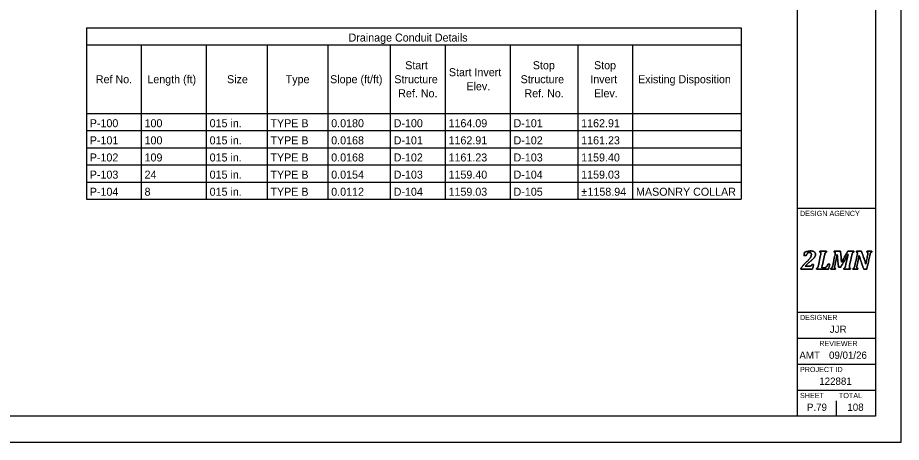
# Model space of a CAD drawing. Extents: x 0 to 34, y 0 to 22.
# Drawn here: x 17 to 34, y 0 to 8.16 of the extents above; entities that cross this region are included whole.
import ezdxf

# ---------------------------------------------------------------- set-up
doc = ezdxf.new("R2010")
doc.units = 0
for name, color, linetype in [('PF_P_Sta_Elev_Text', 7, 'Continuous'), ('SH_Border', 7, 'Continuous'), ('SH_Cut_Line', 7, 'Continuous'), ('SH_Data', 7, 'Continuous')]:
    doc.layers.add(name, color=color, linetype=linetype)

msp = doc.modelspace()

# ---------------------------------------------------------------- linework, layer by layer
at = {"layer": 'PF_P_Sta_Elev_Text'}
for p, q in [((18.321, 7.968), (30.921, 7.968)), ((18.321, 7.968), (18.321, 4.674)), ((30.921, 7.968), (30.921, 4.674)), ((18.321, 7.639), (30.921, 7.639)), ((19.376, 7.639), (19.376, 4.674)), ((20.627, 7.639), (20.627, 4.674)), ((21.797, 7.639), (21.797, 4.674)), ((22.966, 7.639), (22.966, 4.674)), ((24.169, 7.639), (24.169, 4.674)), ((25.223, 7.639), (25.223, 4.674)), ((26.474, 7.639), (26.474, 4.674)), ((27.776, 7.639), (27.776, 4.674)), ((28.83, 7.639), (28.83, 4.674)), ((18.321, 6.321), (30.921, 6.321)), ((18.321, 5.992), (30.921, 5.992)), ((18.321, 5.662), (30.921, 5.662)), ((18.321, 5.333), (30.921, 5.333)), ((18.321, 5.003), (30.921, 5.003)), ((18.321, 4.674), (30.921, 4.674))]:
    msp.add_line(p, q, dxfattribs=at)
at = {"layer": 'SH_Border'}
for p, q in [((32, 0.5), (32, 21.5)), ((32, 4.5), (33.5, 4.5)), ((32, 2.5), (33.5, 2.5)), ((32, 2), (33.5, 2)), ((32, 1.5), (33.5, 1.5)), ((32, 1), (33.5, 1))]:
    msp.add_line(p, q, dxfattribs=at)
msp.add_lwpolyline([(1.5, 21.5), (33.5, 21.5), (33.5, 0.5), (1.5, 0.5)], close=True, dxfattribs=at)
at = {"layer": 'SH_Cut_Line'}
msp.add_lwpolyline([(0, 0), (34, 0), (34, 22), (0, 22)], close=True, dxfattribs=at)
at = {"layer": 'SH_Data'}
for p, q in [((32.75, 3.5), (32.75, 3.5)), ((32.75, 0.5), (32.75, 0.8)), ((32.375, 0.675), (32.375, 0.675))]:
    msp.add_line(p, q, dxfattribs=at)
for points in [[(32.237, 3.388), (32.246, 3.388), (32.253, 3.389), (32.258, 3.39), (32.263, 3.392), (32.267, 3.394), (32.27, 3.397), (32.273, 3.401), (32.277, 3.408), (32.281, 3.417), (32.281, 3.417), (32.312, 3.417), (32.312, 3.417), (32.312, 3.417), (32.29, 3.326), (32.29, 3.326), (32.29, 3.326), (32.066, 3.326), (32.066, 3.326), (32.066, 3.326), (32.069, 3.343), (32.069, 3.343), (32.078, 3.358), (32.091, 3.375), (32.106, 3.394), (32.122, 3.412), (32.144, 3.435), (32.172, 3.462), (32.197, 3.486), (32.217, 3.506), (32.23, 3.521), (32.243, 3.537), (32.253, 3.551), (32.259, 3.566), (32.266, 3.58), (32.269, 3.595), (32.269, 3.61), (32.269, 3.622), (32.266, 3.632), (32.26, 3.64), (32.253, 3.647), (32.245, 3.65), (32.234, 3.65), (32.22, 3.65), (32.208, 3.646), (32.198, 3.636), (32.188, 3.627), (32.18, 3.613), (32.172, 3.593), (32.172, 3.593), (32.126, 3.593), (32.126, 3.593), (32.126, 3.593), (32.14, 3.654), (32.14, 3.654), (32.166, 3.663), (32.188, 3.669), (32.205, 3.673), (32.223, 3.676), (32.24, 3.678), (32.258, 3.678), (32.278, 3.678), (32.295, 3.675), (32.309, 3.669), (32.322, 3.664), (32.332, 3.656), (32.339, 3.646), (32.345, 3.637), (32.348, 3.626), (32.348, 3.613), (32.348, 3.602), (32.346, 3.591), (32.342, 3.581), (32.339, 3.571), (32.333, 3.56), (32.324, 3.549), (32.315, 3.539), (32.304, 3.526), (32.289, 3.513), (32.275, 3.499), (32.254, 3.482), (32.228, 3.46), (32.216, 3.45), (32.202, 3.438), (32.188, 3.425), (32.174, 3.412), (32.162, 3.4), (32.154, 3.391), (32.154, 3.391), (32.153, 3.388), (32.153, 3.388), (32.153, 3.388), (32.237, 3.388), (32.237, 3.388)], [(32.237, 3.388), (32.237, 3.388), (32.153, 3.388), (32.153, 3.388), (32.153, 3.388), (32.154, 3.391), (32.154, 3.391), (32.162, 3.4), (32.174, 3.412), (32.188, 3.425), (32.202, 3.438), (32.216, 3.45), (32.228, 3.46), (32.254, 3.482), (32.275, 3.499), (32.289, 3.513), (32.304, 3.526), (32.315, 3.539), (32.324, 3.549), (32.333, 3.56), (32.339, 3.571), (32.342, 3.581), (32.346, 3.591), (32.348, 3.602), (32.348, 3.613), (32.348, 3.626), (32.345, 3.637), (32.339, 3.646), (32.332, 3.656), (32.322, 3.664), (32.309, 3.669), (32.295, 3.675), (32.278, 3.678), (32.258, 3.678), (32.24, 3.678), (32.223, 3.676), (32.205, 3.673), (32.188, 3.669), (32.166, 3.663), (32.14, 3.654), (32.14, 3.654), (32.126, 3.593), (32.126, 3.593), (32.126, 3.593), (32.172, 3.593), (32.172, 3.593), (32.18, 3.613), (32.188, 3.627), (32.198, 3.636), (32.208, 3.646), (32.22, 3.65), (32.234, 3.65), (32.245, 3.65), (32.253, 3.647), (32.26, 3.64), (32.266, 3.632), (32.269, 3.622), (32.269, 3.61), (32.269, 3.595), (32.266, 3.58), (32.259, 3.566), (32.253, 3.551), (32.243, 3.537), (32.23, 3.521), (32.217, 3.506), (32.197, 3.486), (32.172, 3.462), (32.144, 3.435), (32.122, 3.412), (32.106, 3.394), (32.091, 3.375), (32.078, 3.358), (32.069, 3.343), (32.069, 3.343), (32.066, 3.326), (32.066, 3.326), (32.066, 3.326), (32.29, 3.326), (32.29, 3.326), (32.29, 3.326), (32.312, 3.417), (32.312, 3.417), (32.312, 3.417), (32.281, 3.417), (32.281, 3.417), (32.277, 3.408), (32.273, 3.401), (32.27, 3.397), (32.267, 3.394), (32.263, 3.392), (32.258, 3.39), (32.253, 3.389), (32.246, 3.388), (32.237, 3.388)], [(32.518, 3.356), (32.527, 3.356), (32.533, 3.357), (32.538, 3.358), (32.542, 3.36), (32.546, 3.362), (32.55, 3.365), (32.554, 3.368), (32.558, 3.372), (32.562, 3.377), (32.567, 3.382), (32.571, 3.388), (32.576, 3.397), (32.58, 3.405), (32.585, 3.415), (32.589, 3.427), (32.589, 3.427), (32.624, 3.427), (32.624, 3.427), (32.624, 3.427), (32.598, 3.326), (32.598, 3.326), (32.598, 3.326), (32.365, 3.326), (32.365, 3.326), (32.365, 3.326), (32.369, 3.343), (32.369, 3.343), (32.376, 3.345), (32.381, 3.348), (32.385, 3.351), (32.389, 3.355), (32.392, 3.36), (32.395, 3.366), (32.398, 3.373), (32.4, 3.382), (32.403, 3.395), (32.403, 3.395), (32.449, 3.605), (32.449, 3.605), (32.452, 3.615), (32.453, 3.625), (32.453, 3.635), (32.453, 3.642), (32.451, 3.647), (32.448, 3.651), (32.444, 3.654), (32.439, 3.656), (32.432, 3.657), (32.432, 3.657), (32.435, 3.674), (32.435, 3.674), (32.435, 3.674), (32.563, 3.674), (32.563, 3.674), (32.563, 3.674), (32.559, 3.657), (32.559, 3.657), (32.552, 3.655), (32.547, 3.652), (32.543, 3.649), (32.539, 3.645), (32.536, 3.64), (32.533, 3.634), (32.531, 3.627), (32.528, 3.618), (32.525, 3.605), (32.525, 3.605), (32.47, 3.356), (32.47, 3.356), (32.47, 3.356), (32.518, 3.356), (32.518, 3.356)], [(32.518, 3.356), (32.518, 3.356), (32.47, 3.356), (32.47, 3.356), (32.47, 3.356), (32.525, 3.605), (32.525, 3.605), (32.528, 3.618), (32.531, 3.627), (32.533, 3.634), (32.536, 3.64), (32.539, 3.645), (32.543, 3.649), (32.547, 3.652), (32.552, 3.655), (32.559, 3.657), (32.559, 3.657), (32.563, 3.674), (32.563, 3.674), (32.563, 3.674), (32.435, 3.674), (32.435, 3.674), (32.435, 3.674), (32.432, 3.657), (32.432, 3.657), (32.439, 3.656), (32.444, 3.654), (32.448, 3.651), (32.451, 3.647), (32.453, 3.642), (32.453, 3.635), (32.453, 3.625), (32.452, 3.615), (32.449, 3.605), (32.449, 3.605), (32.403, 3.395), (32.403, 3.395), (32.4, 3.382), (32.398, 3.373), (32.395, 3.366), (32.392, 3.36), (32.389, 3.355), (32.385, 3.351), (32.381, 3.348), (32.376, 3.345), (32.369, 3.343), (32.369, 3.343), (32.365, 3.326), (32.365, 3.326), (32.365, 3.326), (32.598, 3.326), (32.598, 3.326), (32.598, 3.326), (32.624, 3.427), (32.624, 3.427), (32.624, 3.427), (32.589, 3.427), (32.589, 3.427), (32.585, 3.415), (32.58, 3.405), (32.576, 3.397), (32.571, 3.388), (32.567, 3.382), (32.562, 3.377), (32.558, 3.372), (32.554, 3.368), (32.55, 3.365), (32.546, 3.362), (32.542, 3.36), (32.538, 3.358), (32.533, 3.357), (32.527, 3.356), (32.518, 3.356)], [(32.829, 3.674), (32.829, 3.674), (32.849, 3.461), (32.849, 3.461), (32.849, 3.461), (32.969, 3.674), (32.969, 3.674), (32.969, 3.674), (33.087, 3.674), (33.087, 3.674), (33.087, 3.674), (33.084, 3.657), (33.084, 3.657), (33.077, 3.655), (33.071, 3.652), (33.067, 3.649), (33.064, 3.645), (33.06, 3.64), (33.058, 3.634), (33.055, 3.627), (33.052, 3.618), (33.05, 3.605), (33.05, 3.605), (33.003, 3.395), (33.003, 3.395), (33.002, 3.39), (33.002, 3.387), (33.001, 3.384), (33.001, 3.382), (33.001, 3.379), (33, 3.376), (33, 3.373), (33, 3.369), (33, 3.365), (33, 3.358), (33.002, 3.353), (33.005, 3.349), (33.008, 3.346), (33.014, 3.344), (33.021, 3.343), (33.021, 3.343), (33.018, 3.326), (33.018, 3.326), (33.018, 3.326), (32.89, 3.326), (32.89, 3.326), (32.89, 3.326), (32.893, 3.343), (32.893, 3.343), (32.9, 3.345), (32.906, 3.348), (32.91, 3.351), (32.914, 3.355), (32.917, 3.36), (32.919, 3.366), (32.922, 3.373), (32.925, 3.382), (32.928, 3.395), (32.928, 3.395), (32.951, 3.502), (32.951, 3.502), (32.954, 3.513), (32.957, 3.529), (32.962, 3.548), (32.967, 3.568), (32.972, 3.588), (32.978, 3.609), (32.978, 3.609), (32.973, 3.609), (32.973, 3.609), (32.965, 3.594), (32.957, 3.579), (32.948, 3.563), (32.948, 3.563), (32.833, 3.364), (32.833, 3.364), (32.833, 3.364), (32.792, 3.364), (32.792, 3.364), (32.792, 3.364), (32.775, 3.518), (32.775, 3.518), (32.773, 3.537), (32.772, 3.554), (32.77, 3.569), (32.769, 3.583), (32.768, 3.597), (32.768, 3.611), (32.768, 3.611), (32.764, 3.611), (32.764, 3.611), (32.761, 3.596), (32.758, 3.578), (32.755, 3.558), (32.751, 3.538), (32.747, 3.521), (32.744, 3.507), (32.744, 3.507), (32.72, 3.395), (32.72, 3.395), (32.719, 3.39), (32.718, 3.387), (32.718, 3.384), (32.717, 3.382), (32.717, 3.379), (32.717, 3.376), (32.717, 3.373), (32.716, 3.369), (32.716, 3.365), (32.716, 3.358), (32.718, 3.353), (32.721, 3.349), (32.725, 3.346), (32.73, 3.344), (32.738, 3.343), (32.738, 3.343), (32.734, 3.326), (32.734, 3.326), (32.734, 3.326), (32.641, 3.326), (32.641, 3.326), (32.641, 3.326), (32.644, 3.343), (32.644, 3.343), (32.651, 3.345), (32.657, 3.348), (32.661, 3.351), (32.665, 3.355), (32.668, 3.36), (32.67, 3.366), (32.673, 3.373), (32.676, 3.382), (32.679, 3.395), (32.679, 3.395), (32.725, 3.605), (32.725, 3.605), (32.727, 3.615), (32.728, 3.625), (32.728, 3.635), (32.728, 3.642), (32.727, 3.647), (32.723, 3.651), (32.72, 3.654), (32.715, 3.656), (32.707, 3.657), (32.707, 3.657), (32.711, 3.674), (32.711, 3.674), (32.711, 3.674), (32.829, 3.674), (32.829, 3.674)], [(32.829, 3.674), (32.829, 3.674), (32.711, 3.674), (32.711, 3.674), (32.711, 3.674), (32.707, 3.657), (32.707, 3.657), (32.715, 3.656), (32.72, 3.654), (32.723, 3.651), (32.727, 3.647), (32.728, 3.642), (32.728, 3.635), (32.728, 3.625), (32.727, 3.615), (32.725, 3.605), (32.725, 3.605), (32.679, 3.395), (32.679, 3.395), (32.676, 3.382), (32.673, 3.373), (32.67, 3.366), (32.668, 3.36), (32.665, 3.355), (32.661, 3.351), (32.657, 3.348), (32.651, 3.345), (32.644, 3.343), (32.644, 3.343), (32.641, 3.326), (32.641, 3.326), (32.641, 3.326), (32.734, 3.326), (32.734, 3.326), (32.734, 3.326), (32.738, 3.343), (32.738, 3.343), (32.73, 3.344), (32.725, 3.346), (32.721, 3.349), (32.718, 3.353), (32.716, 3.358), (32.716, 3.365), (32.716, 3.369), (32.717, 3.373), (32.717, 3.376), (32.717, 3.379), (32.717, 3.382), (32.718, 3.384), (32.718, 3.387), (32.719, 3.39), (32.72, 3.395), (32.72, 3.395), (32.744, 3.507), (32.744, 3.507), (32.747, 3.521), (32.751, 3.538), (32.755, 3.558), (32.758, 3.578), (32.761, 3.596), (32.764, 3.611), (32.764, 3.611), (32.768, 3.611), (32.768, 3.611), (32.768, 3.597), (32.769, 3.583), (32.77, 3.569), (32.772, 3.554), (32.773, 3.537), (32.775, 3.518), (32.775, 3.518), (32.792, 3.364), (32.792, 3.364), (32.792, 3.364), (32.833, 3.364), (32.833, 3.364), (32.833, 3.364), (32.948, 3.563), (32.948, 3.563), (32.957, 3.579), (32.965, 3.594), (32.973, 3.609), (32.973, 3.609), (32.978, 3.609), (32.978, 3.609), (32.972, 3.588), (32.967, 3.568), (32.962, 3.548), (32.957, 3.529), (32.954, 3.513), (32.951, 3.502), (32.951, 3.502), (32.928, 3.395), (32.928, 3.395), (32.925, 3.382), (32.922, 3.373), (32.919, 3.366), (32.917, 3.36), (32.914, 3.355), (32.91, 3.351), (32.906, 3.348), (32.9, 3.345), (32.893, 3.343), (32.893, 3.343), (32.89, 3.326), (32.89, 3.326), (32.89, 3.326), (33.018, 3.326), (33.018, 3.326), (33.018, 3.326), (33.021, 3.343), (33.021, 3.343), (33.014, 3.344), (33.008, 3.346), (33.005, 3.349), (33.002, 3.353), (33, 3.358), (33, 3.365), (33, 3.369), (33, 3.373), (33, 3.376), (33.001, 3.379), (33.001, 3.382), (33.001, 3.384), (33.002, 3.387), (33.002, 3.39), (33.003, 3.395), (33.003, 3.395), (33.05, 3.605), (33.05, 3.605), (33.052, 3.618), (33.055, 3.627), (33.058, 3.634), (33.06, 3.64), (33.064, 3.645), (33.067, 3.649), (33.071, 3.652), (33.077, 3.655), (33.084, 3.657), (33.084, 3.657), (33.087, 3.674), (33.087, 3.674), (33.087, 3.674), (32.969, 3.674), (32.969, 3.674), (32.969, 3.674), (32.849, 3.461), (32.849, 3.461), (32.849, 3.461), (32.829, 3.674), (32.829, 3.674)], [(33.137, 3.674), (33.137, 3.674), (33.234, 3.674), (33.234, 3.674), (33.234, 3.674), (33.283, 3.53), (33.283, 3.53), (33.296, 3.49), (33.307, 3.456), (33.315, 3.426), (33.315, 3.426), (33.318, 3.426), (33.318, 3.426), (33.323, 3.455), (33.329, 3.488), (33.337, 3.523), (33.337, 3.523), (33.355, 3.605), (33.355, 3.605), (33.357, 3.615), (33.358, 3.625), (33.358, 3.635), (33.358, 3.642), (33.357, 3.647), (33.353, 3.651), (33.35, 3.654), (33.345, 3.656), (33.337, 3.657), (33.337, 3.657), (33.341, 3.674), (33.341, 3.674), (33.341, 3.674), (33.434, 3.674), (33.434, 3.674), (33.434, 3.674), (33.431, 3.657), (33.431, 3.657), (33.424, 3.655), (33.418, 3.652), (33.414, 3.649), (33.41, 3.645), (33.407, 3.64), (33.405, 3.634), (33.402, 3.627), (33.399, 3.618), (33.396, 3.605), (33.396, 3.605), (33.335, 3.326), (33.335, 3.326), (33.335, 3.326), (33.277, 3.326), (33.277, 3.326), (33.277, 3.326), (33.216, 3.504), (33.216, 3.504), (33.211, 3.518), (33.207, 3.531), (33.204, 3.543), (33.2, 3.556), (33.195, 3.571), (33.19, 3.59), (33.19, 3.59), (33.186, 3.59), (33.186, 3.59), (33.185, 3.579), (33.182, 3.563), (33.179, 3.543), (33.175, 3.523), (33.17, 3.501), (33.165, 3.478), (33.165, 3.478), (33.147, 3.395), (33.147, 3.395), (33.146, 3.39), (33.145, 3.387), (33.145, 3.384), (33.144, 3.382), (33.144, 3.379), (33.144, 3.376), (33.143, 3.373), (33.143, 3.369), (33.143, 3.365), (33.143, 3.358), (33.145, 3.353), (33.148, 3.349), (33.152, 3.346), (33.157, 3.344), (33.164, 3.343), (33.164, 3.343), (33.161, 3.326), (33.161, 3.326), (33.161, 3.326), (33.067, 3.326), (33.067, 3.326), (33.067, 3.326), (33.071, 3.343), (33.071, 3.343), (33.078, 3.345), (33.083, 3.348), (33.087, 3.351), (33.091, 3.355), (33.094, 3.36), (33.097, 3.366), (33.1, 3.373), (33.102, 3.382), (33.105, 3.395), (33.105, 3.395), (33.151, 3.605), (33.151, 3.605), (33.154, 3.615), (33.155, 3.625), (33.155, 3.635), (33.155, 3.642), (33.153, 3.647), (33.15, 3.651), (33.146, 3.654), (33.141, 3.656), (33.134, 3.657), (33.134, 3.657), (33.137, 3.674), (33.137, 3.674)], [(33.137, 3.674), (33.137, 3.674), (33.134, 3.657), (33.134, 3.657), (33.141, 3.656), (33.146, 3.654), (33.15, 3.651), (33.153, 3.647), (33.155, 3.642), (33.155, 3.635), (33.155, 3.625), (33.154, 3.615), (33.151, 3.605), (33.151, 3.605), (33.105, 3.395), (33.105, 3.395), (33.102, 3.382), (33.1, 3.373), (33.097, 3.366), (33.094, 3.36), (33.091, 3.355), (33.087, 3.351), (33.083, 3.348), (33.078, 3.345), (33.071, 3.343), (33.071, 3.343), (33.067, 3.326), (33.067, 3.326), (33.067, 3.326), (33.161, 3.326), (33.161, 3.326), (33.161, 3.326), (33.164, 3.343), (33.164, 3.343), (33.157, 3.344), (33.152, 3.346), (33.148, 3.349), (33.145, 3.353), (33.143, 3.358), (33.143, 3.365), (33.143, 3.369), (33.143, 3.373), (33.144, 3.376), (33.144, 3.379), (33.144, 3.382), (33.145, 3.384), (33.145, 3.387), (33.146, 3.39), (33.147, 3.395), (33.147, 3.395), (33.165, 3.478), (33.165, 3.478), (33.17, 3.501), (33.175, 3.523), (33.179, 3.543), (33.182, 3.563), (33.185, 3.579), (33.186, 3.59), (33.186, 3.59), (33.19, 3.59), (33.19, 3.59), (33.195, 3.571), (33.2, 3.556), (33.204, 3.543), (33.207, 3.531), (33.211, 3.518), (33.216, 3.504), (33.216, 3.504), (33.277, 3.326), (33.277, 3.326), (33.277, 3.326), (33.335, 3.326), (33.335, 3.326), (33.335, 3.326), (33.396, 3.605), (33.396, 3.605), (33.399, 3.618), (33.402, 3.627), (33.405, 3.634), (33.407, 3.64), (33.41, 3.645), (33.414, 3.649), (33.418, 3.652), (33.424, 3.655), (33.431, 3.657), (33.431, 3.657), (33.434, 3.674), (33.434, 3.674), (33.434, 3.674), (33.341, 3.674), (33.341, 3.674), (33.341, 3.674), (33.337, 3.657), (33.337, 3.657), (33.345, 3.656), (33.35, 3.654), (33.353, 3.651), (33.357, 3.647), (33.358, 3.642), (33.358, 3.635), (33.358, 3.625), (33.357, 3.615), (33.355, 3.605), (33.355, 3.605), (33.337, 3.523), (33.337, 3.523), (33.329, 3.488), (33.323, 3.455), (33.318, 3.426), (33.318, 3.426), (33.315, 3.426), (33.315, 3.426), (33.307, 3.456), (33.296, 3.49), (33.283, 3.53), (33.283, 3.53), (33.234, 3.674), (33.234, 3.674), (33.234, 3.674), (33.137, 3.674), (33.137, 3.674)]]:
    msp.add_open_spline(points, degree=3, dxfattribs=at)

# ---------------------------------------------------------------- texts
at = {"layer": 'PF_P_Sta_Elev_Text'}
for s, p in [('Drainage Conduit Details', (23.366, 7.704)), ('Start ', (24.456, 7.172)), ('Stop ', (26.911, 7.172)), ('Stop ', (28.088, 7.172)), ('Start Invert ', (25.296, 7.038)), ('Ref No.', (18.504, 6.903)), ('Length (ft)', (19.495, 6.903)), ('Size', (21.028, 6.903)), ('Type', (22.156, 6.903)), ('Slope (ft/ft)', (23.011, 6.903)), ('Structure ', (24.246, 6.903)), ('Structure ', (26.676, 6.903)), ('Invert ', (28.016, 6.903)), ('Existing Disposition', (28.935, 6.903)), ('Elev.', (25.633, 6.768)), ('Ref. No.', (24.321, 6.633)), ('Ref. No.', (26.75, 6.633)), ('Elev.', (28.087, 6.633)), ('P-100', (18.387, 6.057)), ('100', (19.441, 6.057)), ('015 in.', (20.693, 6.057)), ('TYPE B', (21.863, 6.057)), ('0.0180', (23.032, 6.057)), ('D-100', (24.234, 6.057)), ('1164.09', (25.289, 6.057)), ('D-101', (26.54, 6.057)), ('1162.91', (27.841, 6.057)), ('P-101', (18.387, 5.728)), ('100', (19.441, 5.728)), ('015 in.', (20.693, 5.728)), ('TYPE B', (21.863, 5.728)), ('0.0168', (23.032, 5.728)), ('D-101', (24.234, 5.728)), ('1162.91', (25.289, 5.728)), ('D-102', (26.54, 5.728)), ('1161.23', (27.841, 5.728)), ('P-102', (18.387, 5.399)), ('109', (19.441, 5.399)), ('015 in.', (20.693, 5.399)), ('TYPE B', (21.863, 5.399)), ('0.0168', (23.032, 5.399)), ('D-102', (24.234, 5.399)), ('1161.23', (25.289, 5.399)), ('D-103', (26.54, 5.399)), ('1159.40', (27.841, 5.399)), ('P-103', (18.387, 5.069)), ('24', (19.441, 5.069)), ('015 in.', (20.693, 5.069)), ('TYPE B', (21.863, 5.069)), ('0.0154', (23.032, 5.069)), ('D-103', (24.234, 5.069)), ('1159.40', (25.289, 5.069)), ('D-104', (26.54, 5.069)), ('1159.03', (27.841, 5.069)), ('P-104', (18.387, 4.74)), ('8', (19.441, 4.74)), ('015 in.', (20.693, 4.74)), ('TYPE B', (21.863, 4.74)), ('0.0112', (23.032, 4.74)), ('D-104', (24.234, 4.74)), ('1159.03', (25.289, 4.74)), ('D-105', (26.54, 4.74)), ('±', (27.841, 4.74)), ('1158.94', (27.962, 4.74)), ('MASONRY COLLAR', (28.896, 4.74))]:
    msp.add_text(s, height=0.154, dxfattribs=at).set_placement(p)
at = {"layer": 'SH_Data'}
for s, height, p in [('DESIGN AGENCY', 0.1, (32.05, 4.35)), ('DESIGNER', 0.1, (32.05, 2.35)), ('JJR', 0.14, (32.624, 2.105)), ('REVIEWER', 0.1, (32.422, 1.85)), ('AMT', 0.14, (32.039, 1.605)), ('09/01/26', 0.14, (32.609, 1.605)), ('PROJECT ID', 0.1, (32.05, 1.35)), ('122881', 0.14, (32.421, 1.105)), ('SHEET', 0.1, (32.05, 0.85)), ('TOTAL', 0.1, (32.8, 0.85)), ('P.79', 0.14, (32.184, 0.605)), ('108', 0.14, (32.962, 0.605))]:
    msp.add_text(s, height=height, dxfattribs=at).set_placement(p)

doc.saveas('drawing.dxf')
